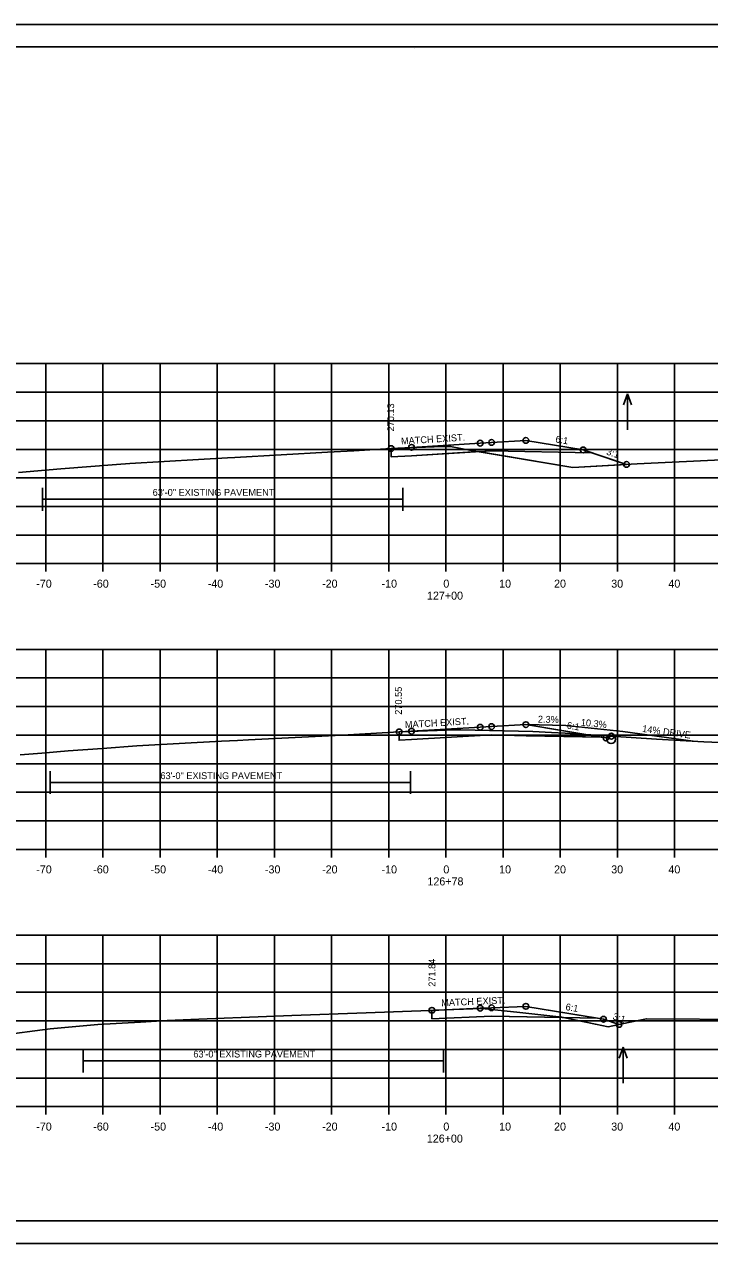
# Model space of a CAD drawing. Extents: x 1103485 to 1107180, y 2010593 to 2011873.
# Drawn here: x 1106943.4 to 1107063.3, y 2010806.2 to 2011019.5 of the extents above; entities that cross this region are included whole.
import ezdxf

# ---------------------------------------------------------------- set-up
doc = ezdxf.new("R2010")
doc.units = 0
for name, color, linetype in [('R_Alt Surface', 7, 'Continuous'), ('R_Axis', 7, 'Continuous'), ('R_Axis Annot', 7, 'Continuous'), ('R_Border', 7, 'Continuous'), ('R_Contours', 7, 'Continuous'), ('R_Dimension', 7, 'Continuous'), ('R_Drive', 7, 'Continuous'), ('R_Exist Surface', 7, 'Continuous'), ('R_Fin Surface', 7, 'Continuous'), ('R_Grid', 7, 'Continuous'), ('R_No Plot', 7, 'Continuous'), ('R_Proposed Const Limits', 7, 'Continuous'), ('R_Water', 7, 'Continuous'), ('R_Water Annot', 7, 'Continuous'), ('R_Xsect Elev', 7, 'Continuous'), ('R_Xsect Slope', 7, 'Continuous')]:
    doc.layers.add(name, color=color, linetype=linetype)

msp = doc.modelspace()

# ---------------------------------------------------------------- linework, layer by layer
at = {"layer": 'R_Alt Surface'}
for points in [[(1107007.62, 2010945.28), (1107007.62, 2010943.82), (1107011.18, 2010944.04), (1107025.18, 2010944.89), (1107042.72, 2010944.54)], [(1107008.98, 2010895.71), (1107008.98, 2010894.25), (1107011.18, 2010894.37), (1107025.18, 2010895.17), (1107044.31, 2010894.79)], [(1107014.74, 2010846.99), (1107014.74, 2010845.53), (1107025.18, 2010845.98), (1107043.7, 2010845.61)]]:
    msp.add_lwpolyline(points, dxfattribs=at)
at = {"layer": 'R_Axis'}
for p, q in [((1106867.18, 2010925.15), (1107167.18, 2010925.15)), ((1106947.18, 2010923.75), (1106947.18, 2010925.15)), ((1106957.18, 2010923.75), (1106957.18, 2010925.15)), ((1106967.18, 2010923.75), (1106967.18, 2010925.15)), ((1106977.18, 2010923.75), (1106977.18, 2010925.15)), ((1106987.18, 2010923.75), (1106987.18, 2010925.15)), ((1106997.18, 2010923.75), (1106997.18, 2010925.15)), ((1107007.18, 2010923.75), (1107007.18, 2010925.15)), ((1107017.18, 2010923.75), (1107017.18, 2010925.15)), ((1107027.18, 2010923.75), (1107027.18, 2010925.15)), ((1107037.18, 2010923.75), (1107037.18, 2010925.15)), ((1107047.18, 2010923.75), (1107047.18, 2010925.15)), ((1107057.18, 2010923.75), (1107057.18, 2010925.15)), ((1106867.18, 2010875.15), (1107167.18, 2010875.15)), ((1106947.18, 2010873.75), (1106947.18, 2010875.15)), ((1106957.18, 2010873.75), (1106957.18, 2010875.15)), ((1106967.18, 2010873.75), (1106967.18, 2010875.15)), ((1106977.18, 2010873.75), (1106977.18, 2010875.15)), ((1106987.18, 2010873.75), (1106987.18, 2010875.15)), ((1106997.18, 2010873.75), (1106997.18, 2010875.15)), ((1107007.18, 2010873.75), (1107007.18, 2010875.15)), ((1107017.18, 2010873.75), (1107017.18, 2010875.15)), ((1107027.18, 2010873.75), (1107027.18, 2010875.15)), ((1107037.18, 2010873.75), (1107037.18, 2010875.15)), ((1107047.18, 2010873.75), (1107047.18, 2010875.15)), ((1107057.18, 2010873.75), (1107057.18, 2010875.15)), ((1106867.18, 2010830.15), (1107167.18, 2010830.15)), ((1106947.18, 2010828.75), (1106947.18, 2010830.15)), ((1106957.18, 2010828.75), (1106957.18, 2010830.15)), ((1106967.18, 2010828.75), (1106967.18, 2010830.15)), ((1106977.18, 2010828.75), (1106977.18, 2010830.15)), ((1106987.18, 2010828.75), (1106987.18, 2010830.15)), ((1106997.18, 2010828.75), (1106997.18, 2010830.15)), ((1107007.18, 2010828.75), (1107007.18, 2010830.15)), ((1107017.18, 2010828.75), (1107017.18, 2010830.15)), ((1107027.18, 2010828.75), (1107027.18, 2010830.15)), ((1107037.18, 2010828.75), (1107037.18, 2010830.15)), ((1107047.18, 2010828.75), (1107047.18, 2010830.15)), ((1107057.18, 2010828.75), (1107057.18, 2010830.15))]:
    msp.add_line(p, q, dxfattribs=at)
at = {"layer": 'R_Border'}
for p, q in [((1106859.18, 2011015.61), (1107175.36, 2011015.61)), ((1107011.7, 2011015.35), (1107011.7, 2011015.35)), ((1107011.7, 2011015.35), (1107011.7, 2011015.35)), ((1107175.36, 2010810.15), (1106859.18, 2010810.15))]:
    msp.add_line(p, q, dxfattribs=at)
at = {"layer": 'R_Contours'}
for points in [[(1107007.62, 2010945.28), (1107016.65, 2010945.64), (1107017.26, 2010945.66), (1107017.99, 2010945.67), (1107021.6, 2010944.96), (1107022.84, 2010944.75), (1107011.18, 2010944.04), (1107007.62, 2010943.82)], [(1107022.84, 2010944.75), (1107039.4, 2010941.98), (1107048.79, 2010942.52), (1107042.72, 2010944.54), (1107025.18, 2010944.89)], [(1107008.98, 2010895.71), (1107017.28, 2010896.04), (1107018.21, 2010896.08), (1107018.46, 2010896.08), (1107018.81, 2010896.07), (1107019.78, 2010896.05), (1107032.36, 2010895.8), (1107035.63, 2010895.63), (1107038.06, 2010895.49), (1107046.12, 2010894.96), (1107045.18, 2010894.65), (1107044.31, 2010894.79), (1107031.24, 2010895.05), (1107025.18, 2010895.17), (1107011.18, 2010894.37), (1107008.98, 2010894.25)], [(1107014.74, 2010846.99), (1107015.32, 2010847.02), (1107023.55, 2010847.33), (1107030.1, 2010846.59), (1107037.47, 2010845.77), (1107037.67, 2010845.73), (1107025.18, 2010845.98), (1107014.74, 2010845.53)], [(1107037.67, 2010845.73), (1107043.32, 2010844.57), (1107045.55, 2010844.12), (1107047.46, 2010844.52), (1107044.74, 2010845.43), (1107043.7, 2010845.61)]]:
    msp.add_lwpolyline(points, close=True, dxfattribs=at)
at = {"layer": 'R_Dimension'}
for p, q in [((1106946.62, 2010938.42), (1106946.62, 2010934.42)), ((1107009.62, 2010938.42), (1107009.62, 2010934.42)), ((1106946.62, 2010936.42), (1107009.62, 2010936.42)), ((1106947.98, 2010888.85), (1106947.98, 2010884.85)), ((1107010.98, 2010888.85), (1107010.98, 2010884.85)), ((1106947.98, 2010886.85), (1107010.98, 2010886.85)), ((1106953.74, 2010840.14), (1106953.74, 2010836.14)), ((1107016.74, 2010840.14), (1107016.74, 2010836.14)), ((1106953.74, 2010838.14), (1107016.74, 2010838.14))]:
    msp.add_line(p, q, dxfattribs=at)
at = {"layer": 'R_Drive'}
for p, q in [((1107031.18, 2010896.98), (1107038.18, 2010896.82)), ((1107038.18, 2010896.82), (1107048.13, 2010895.8)), ((1107048.13, 2010895.8), (1107060.44, 2010894.08))]:
    msp.add_line(p, q, dxfattribs=at)
at = {"layer": 'R_Exist Surface'}
for points in [[(1106942.4, 2010941.11), (1106949.81, 2010941.74), (1106959.58, 2010942.48), (1106961.91, 2010942.65), (1106973.92, 2010943.36), (1106979, 2010943.67), (1106980.24, 2010943.74), (1106996.44, 2010944.63), (1107001.06, 2010944.9), (1107007.62, 2010945.28), (1107016.65, 2010945.64), (1107017.26, 2010945.66), (1107017.99, 2010945.67), (1107021.6, 2010944.96), (1107039.4, 2010941.98), (1107050.66, 2010942.63), (1107066.6, 2010943.35)], [(1106942.7, 2010891.69), (1106946.49, 2010892), (1106951.11, 2010892.38), (1106957.1, 2010892.82), (1106963.14, 2010893.25), (1106977.94, 2010894.07), (1106980.75, 2010894.22), (1106982.62, 2010894.31), (1106997.82, 2010895.08), (1107000.07, 2010895.2), (1107008.98, 2010895.71), (1107017.28, 2010896.04), (1107018.21, 2010896.08), (1107018.46, 2010896.08), (1107018.81, 2010896.07), (1107019.78, 2010896.05), (1107032.36, 2010895.8), (1107035.63, 2010895.63), (1107038.06, 2010895.49), (1107053.99, 2010894.44), (1107062.32, 2010893.97), (1107067.87, 2010893.72)], [(1106939, 2010842.61), (1106947.97, 2010843.77), (1106951.18, 2010844.05), (1106956.27, 2010844.51), (1106963.77, 2010844.94), (1106968.4, 2010845.22), (1106973.95, 2010845.44), (1106985.8, 2010845.89), (1106990.24, 2010846.06), (1107003.23, 2010846.55), (1107014.36, 2010846.98), (1107014.74, 2010846.99), (1107015.32, 2010847.02), (1107023.55, 2010847.33), (1107030.1, 2010846.59), (1107037.47, 2010845.77), (1107043.32, 2010844.57), (1107045.55, 2010844.12), (1107049.13, 2010844.88), (1107052.24, 2010845.53), (1107070.89, 2010845.37)]]:
    msp.add_lwpolyline(points, dxfattribs=at)
at = {"layer": 'R_Fin Surface'}
for points in [[(1107007.62, 2010945.28), (1107011.18, 2010945.5), (1107023.18, 2010946.23), (1107025.18, 2010946.36), (1107031.18, 2010946.72), (1107041.18, 2010945.06), (1107042.72, 2010944.54), (1107048.79, 2010942.52)], [(1107007.62, 2010945.28), (1107011.18, 2010945.5), (1107023.18, 2010946.23), (1107025.18, 2010946.36), (1107031.18, 2010946.72)], [(1107008.98, 2010895.71), (1107011.18, 2010895.83), (1107023.18, 2010896.52), (1107025.18, 2010896.64), (1107031.18, 2010896.98)], [(1107008.98, 2010895.71), (1107011.18, 2010895.83), (1107023.18, 2010896.52), (1107025.18, 2010896.64), (1107031.18, 2010896.98), (1107044.31, 2010894.79), (1107045.18, 2010894.65), (1107046.12, 2010894.96)], [(1107014.74, 2010846.99), (1107023.18, 2010847.35), (1107025.18, 2010847.44), (1107031.18, 2010847.69), (1107043.7, 2010845.61), (1107044.74, 2010845.43), (1107047.46, 2010844.52)], [(1107014.74, 2010846.99), (1107023.18, 2010847.35), (1107025.18, 2010847.44), (1107031.18, 2010847.69)]]:
    msp.add_lwpolyline(points, dxfattribs=at)
at = {"layer": 'R_Grid'}
for p, q in [((1106867.18, 2010960.15), (1107167.18, 2010960.15)), ((1106947.18, 2010925.15), (1106947.18, 2010960.15)), ((1106957.18, 2010925.15), (1106957.18, 2010960.15)), ((1106967.18, 2010925.15), (1106967.18, 2010960.15)), ((1106977.18, 2010925.15), (1106977.18, 2010960.15)), ((1106987.18, 2010925.15), (1106987.18, 2010960.15)), ((1106997.18, 2010925.15), (1106997.18, 2010960.15)), ((1107007.18, 2010925.15), (1107007.18, 2010960.15)), ((1107017.18, 2010925.15), (1107017.18, 2010960.15)), ((1107027.18, 2010925.15), (1107027.18, 2010960.15)), ((1107037.18, 2010925.15), (1107037.18, 2010960.15)), ((1107047.18, 2010925.15), (1107047.18, 2010960.15)), ((1107057.18, 2010925.15), (1107057.18, 2010960.15)), ((1106867.18, 2010955.15), (1107167.18, 2010955.15)), ((1106867.18, 2010950.15), (1107167.18, 2010950.15)), ((1106867.18, 2010945.15), (1107167.18, 2010945.15)), ((1106867.18, 2010940.15), (1107167.18, 2010940.15)), ((1106867.18, 2010935.15), (1107167.18, 2010935.15)), ((1106867.18, 2010930.15), (1107167.18, 2010930.15)), ((1106867.18, 2010925.15), (1107167.18, 2010925.15)), ((1106867.18, 2010910.15), (1107167.18, 2010910.15)), ((1106947.18, 2010875.15), (1106947.18, 2010910.15)), ((1106957.18, 2010875.15), (1106957.18, 2010910.15)), ((1106967.18, 2010875.15), (1106967.18, 2010910.15)), ((1106977.18, 2010875.15), (1106977.18, 2010910.15)), ((1106987.18, 2010875.15), (1106987.18, 2010910.15)), ((1106997.18, 2010875.15), (1106997.18, 2010910.15)), ((1107007.18, 2010875.15), (1107007.18, 2010910.15)), ((1107017.18, 2010875.15), (1107017.18, 2010910.15)), ((1107027.18, 2010875.15), (1107027.18, 2010910.15)), ((1107037.18, 2010875.15), (1107037.18, 2010910.15)), ((1107047.18, 2010875.15), (1107047.18, 2010910.15)), ((1107057.18, 2010875.15), (1107057.18, 2010910.15)), ((1106867.18, 2010905.15), (1107167.18, 2010905.15)), ((1106867.18, 2010900.15), (1107167.18, 2010900.15)), ((1106867.18, 2010895.15), (1107167.18, 2010895.15)), ((1106867.18, 2010890.15), (1107167.18, 2010890.15)), ((1106867.18, 2010885.15), (1107167.18, 2010885.15)), ((1106867.18, 2010880.15), (1107167.18, 2010880.15)), ((1106867.18, 2010875.15), (1107167.18, 2010875.15)), ((1106867.18, 2010860.15), (1107167.18, 2010860.15)), ((1106947.18, 2010830.15), (1106947.18, 2010860.15)), ((1106957.18, 2010830.15), (1106957.18, 2010860.15)), ((1106967.18, 2010830.15), (1106967.18, 2010860.15)), ((1106977.18, 2010830.15), (1106977.18, 2010860.15)), ((1106987.18, 2010830.15), (1106987.18, 2010860.15)), ((1106997.18, 2010830.15), (1106997.18, 2010860.15)), ((1107007.18, 2010830.15), (1107007.18, 2010860.15)), ((1107017.18, 2010830.15), (1107017.18, 2010860.15)), ((1107027.18, 2010830.15), (1107027.18, 2010860.15)), ((1107037.18, 2010830.15), (1107037.18, 2010860.15)), ((1107047.18, 2010830.15), (1107047.18, 2010860.15)), ((1107057.18, 2010830.15), (1107057.18, 2010860.15)), ((1106867.18, 2010855.15), (1107167.18, 2010855.15)), ((1106867.18, 2010850.15), (1107167.18, 2010850.15)), ((1106867.18, 2010845.15), (1107167.18, 2010845.15)), ((1106867.18, 2010840.15), (1107167.18, 2010840.15)), ((1106867.18, 2010835.15), (1107167.18, 2010835.15)), ((1106867.18, 2010830.15), (1107167.18, 2010830.15))]:
    msp.add_line(p, q, dxfattribs=at)
at = {"layer": 'R_No Plot'}
for p, q in [((1106846.78, 2011019.51), (1107180.12, 2011019.51)), ((1106846.78, 2010806.18), (1107180.12, 2010806.18))]:
    msp.add_line(p, q, dxfattribs=at)
for points in [[(1106846.78, 2011019.51), (1107180.12, 2011019.51), (1107180.12, 2010806.17), (1106846.78, 2010806.17)], [(1107093.1, 2011015.61), (1107093.1, 2011005.73), (1107128.84, 2011005.73), (1107128.84, 2011002.81), (1107152.04, 2011002.81), (1107152.04, 2010978.48), (1107175.36, 2010978.48), (1107175.36, 2010810.15), (1106859.18, 2010810.15), (1106859.18, 2011015.61)]]:
    msp.add_lwpolyline(points, close=True, dxfattribs=at)
for centre in [(1107011.18, 2010945.5), (1107023.18, 2010946.23), (1107025.18, 2010946.36), (1107031.18, 2010946.72), (1107007.62, 2010945.28), (1107041.18, 2010945.06), (1107048.79, 2010942.52), (1107023.18, 2010896.52), (1107025.18, 2010896.64), (1107031.18, 2010896.98), (1107008.98, 2010895.71), (1107011.18, 2010895.83), (1107045.18, 2010894.65), (1107046.12, 2010894.96), (1107023.18, 2010847.35), (1107025.18, 2010847.44), (1107031.18, 2010847.69), (1107014.74, 2010846.99), (1107044.74, 2010845.43), (1107047.46, 2010844.52)]:
    msp.add_circle(centre, 0.5, dxfattribs=at)
at = {"layer": 'R_Proposed Const Limits'}
for points in [[(1107031.18, 2010946.72), (1107041.18, 2010945.06), (1107048.79, 2010942.52)], [(1107031.18, 2010896.98), (1107045.18, 2010894.65), (1107046.12, 2010894.96)], [(1107031.18, 2010847.69), (1107044.74, 2010845.43), (1107047.46, 2010844.52)]]:
    msp.add_lwpolyline(points, dxfattribs=at)
at = {"layer": 'R_Water'}
for radius in [0.755, 0.75]:
    msp.add_circle((1107046.07, 2010894.41), radius, dxfattribs=at)
at = {"layer": 'R_Water Annot'}
for p, q in [((1107048.95, 2010954.87), (1107048.25, 2010952.95)), ((1107048.95, 2010948.59), (1107048.95, 2010954.87)), ((1107048.95, 2010954.87), (1107049.65, 2010952.95)), ((1107048.18, 2010840.55), (1107047.48, 2010838.63)), ((1107048.18, 2010834.27), (1107048.18, 2010840.55)), ((1107048.18, 2010840.55), (1107048.88, 2010838.63))]:
    msp.add_line(p, q, dxfattribs=at)

# ---------------------------------------------------------------- texts
at = {"layer": 'R_Axis Annot'}
for s, p in [('-70', (1106945.52, 2010920.95)), ('-60', (1106955.49, 2010920.95)), ('-50', (1106965.52, 2010920.95)), ('-40', (1106975.52, 2010920.95)), ('-30', (1106985.52, 2010920.95)), ('-20', (1106995.52, 2010920.95)), ('-10', (1107005.92, 2010920.95)), ('0', (1107016.73, 2010920.95)), ('10', (1107026.49, 2010920.95)), ('20', (1107036.1, 2010920.95)), ('30', (1107046.1, 2010920.95)), ('40', (1107056.1, 2010920.95)), ('127+00', (1107013.87, 2010918.85)), ('-70', (1106945.52, 2010870.95)), ('-60', (1106955.49, 2010870.95)), ('-50', (1106965.52, 2010870.95)), ('-40', (1106975.52, 2010870.95)), ('-30', (1106985.52, 2010870.95)), ('-20', (1106995.52, 2010870.95)), ('-10', (1107005.92, 2010870.95)), ('0', (1107016.73, 2010870.95)), ('10', (1107026.49, 2010870.95)), ('20', (1107036.1, 2010870.95)), ('30', (1107046.1, 2010870.95)), ('40', (1107056.1, 2010870.95)), ('126+78', (1107013.95, 2010868.85)), ('-70', (1106945.52, 2010825.95)), ('-60', (1106955.49, 2010825.95)), ('-50', (1106965.52, 2010825.95)), ('-40', (1106975.52, 2010825.95)), ('-30', (1106985.52, 2010825.95)), ('-20', (1106995.52, 2010825.95)), ('-10', (1107005.92, 2010825.95)), ('0', (1107016.73, 2010825.95)), ('10', (1107026.49, 2010825.95)), ('20', (1107036.1, 2010825.95)), ('30', (1107046.1, 2010825.95)), ('40', (1107056.1, 2010825.95)), ('126+00', (1107013.84, 2010823.85))]:
    msp.add_text(s, height=1.4, dxfattribs=at).set_placement(p)
at = {"layer": 'R_Dimension'}
for p in [(1106965.88, 2010937.02), (1106967.24, 2010887.45), (1106973, 2010838.74)]:
    msp.add_text('63\'-0" EXISTING PAVEMENT', height=1.2, dxfattribs=at).set_placement(p)
at = {"layer": 'R_Drive'}
for s, rotation, p in [('2.3%', 358.568, (1107033.26, 2010897.35)), ('10.3%', 354.139, (1107040.73, 2010896.82)), ('14% DRIVE', 352.03, (1107051.46, 2010895.72))]:
    msp.add_text(s, height=1.2, rotation=rotation, dxfattribs=at).set_placement(p)
at = {"layer": 'R_Xsect Elev'}
for s, p in [('270.13', (1107008.12, 2010948.28)), ('270.55', (1107009.48, 2010898.71)), ('271.84', (1107015.34, 2010851.12))]:
    msp.add_text(s, height=1.2, rotation=90, dxfattribs=at).set_placement(p)
at = {"layer": 'R_Xsect Slope'}
for s, rotation, p in [('MATCH EXIST.', 3.5028, (1107009.36, 2010945.99)), ('6:1', 350.5358, (1107036.27, 2010946.38)), ('3:1', 341.5668, (1107045.15, 2010944.26)), ('MATCH EXIST.', 3.287, (1107010.04, 2010896.37)), ('6:1', 350.5358, (1107038.27, 2010896.31)), ('MATCH EXIST.', 2.4298, (1107016.39, 2010847.7)), ('6:1', 350.5358, (1107038.04, 2010847.05)), ('3:1', 341.5668, (1107046.26, 2010845.45))]:
    msp.add_text(s, height=1.2, rotation=rotation, dxfattribs=at).set_placement(p)

doc.saveas('drawing.dxf')
